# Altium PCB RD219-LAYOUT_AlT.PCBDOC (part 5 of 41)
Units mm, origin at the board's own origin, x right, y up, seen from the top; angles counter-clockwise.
Board outline 209.75 x 159.97 mm, 2 copper layers (TOP, BOTTOM), stack 0 mm thick; 398 components, 199 nets, 1469 pads, 0 vias.
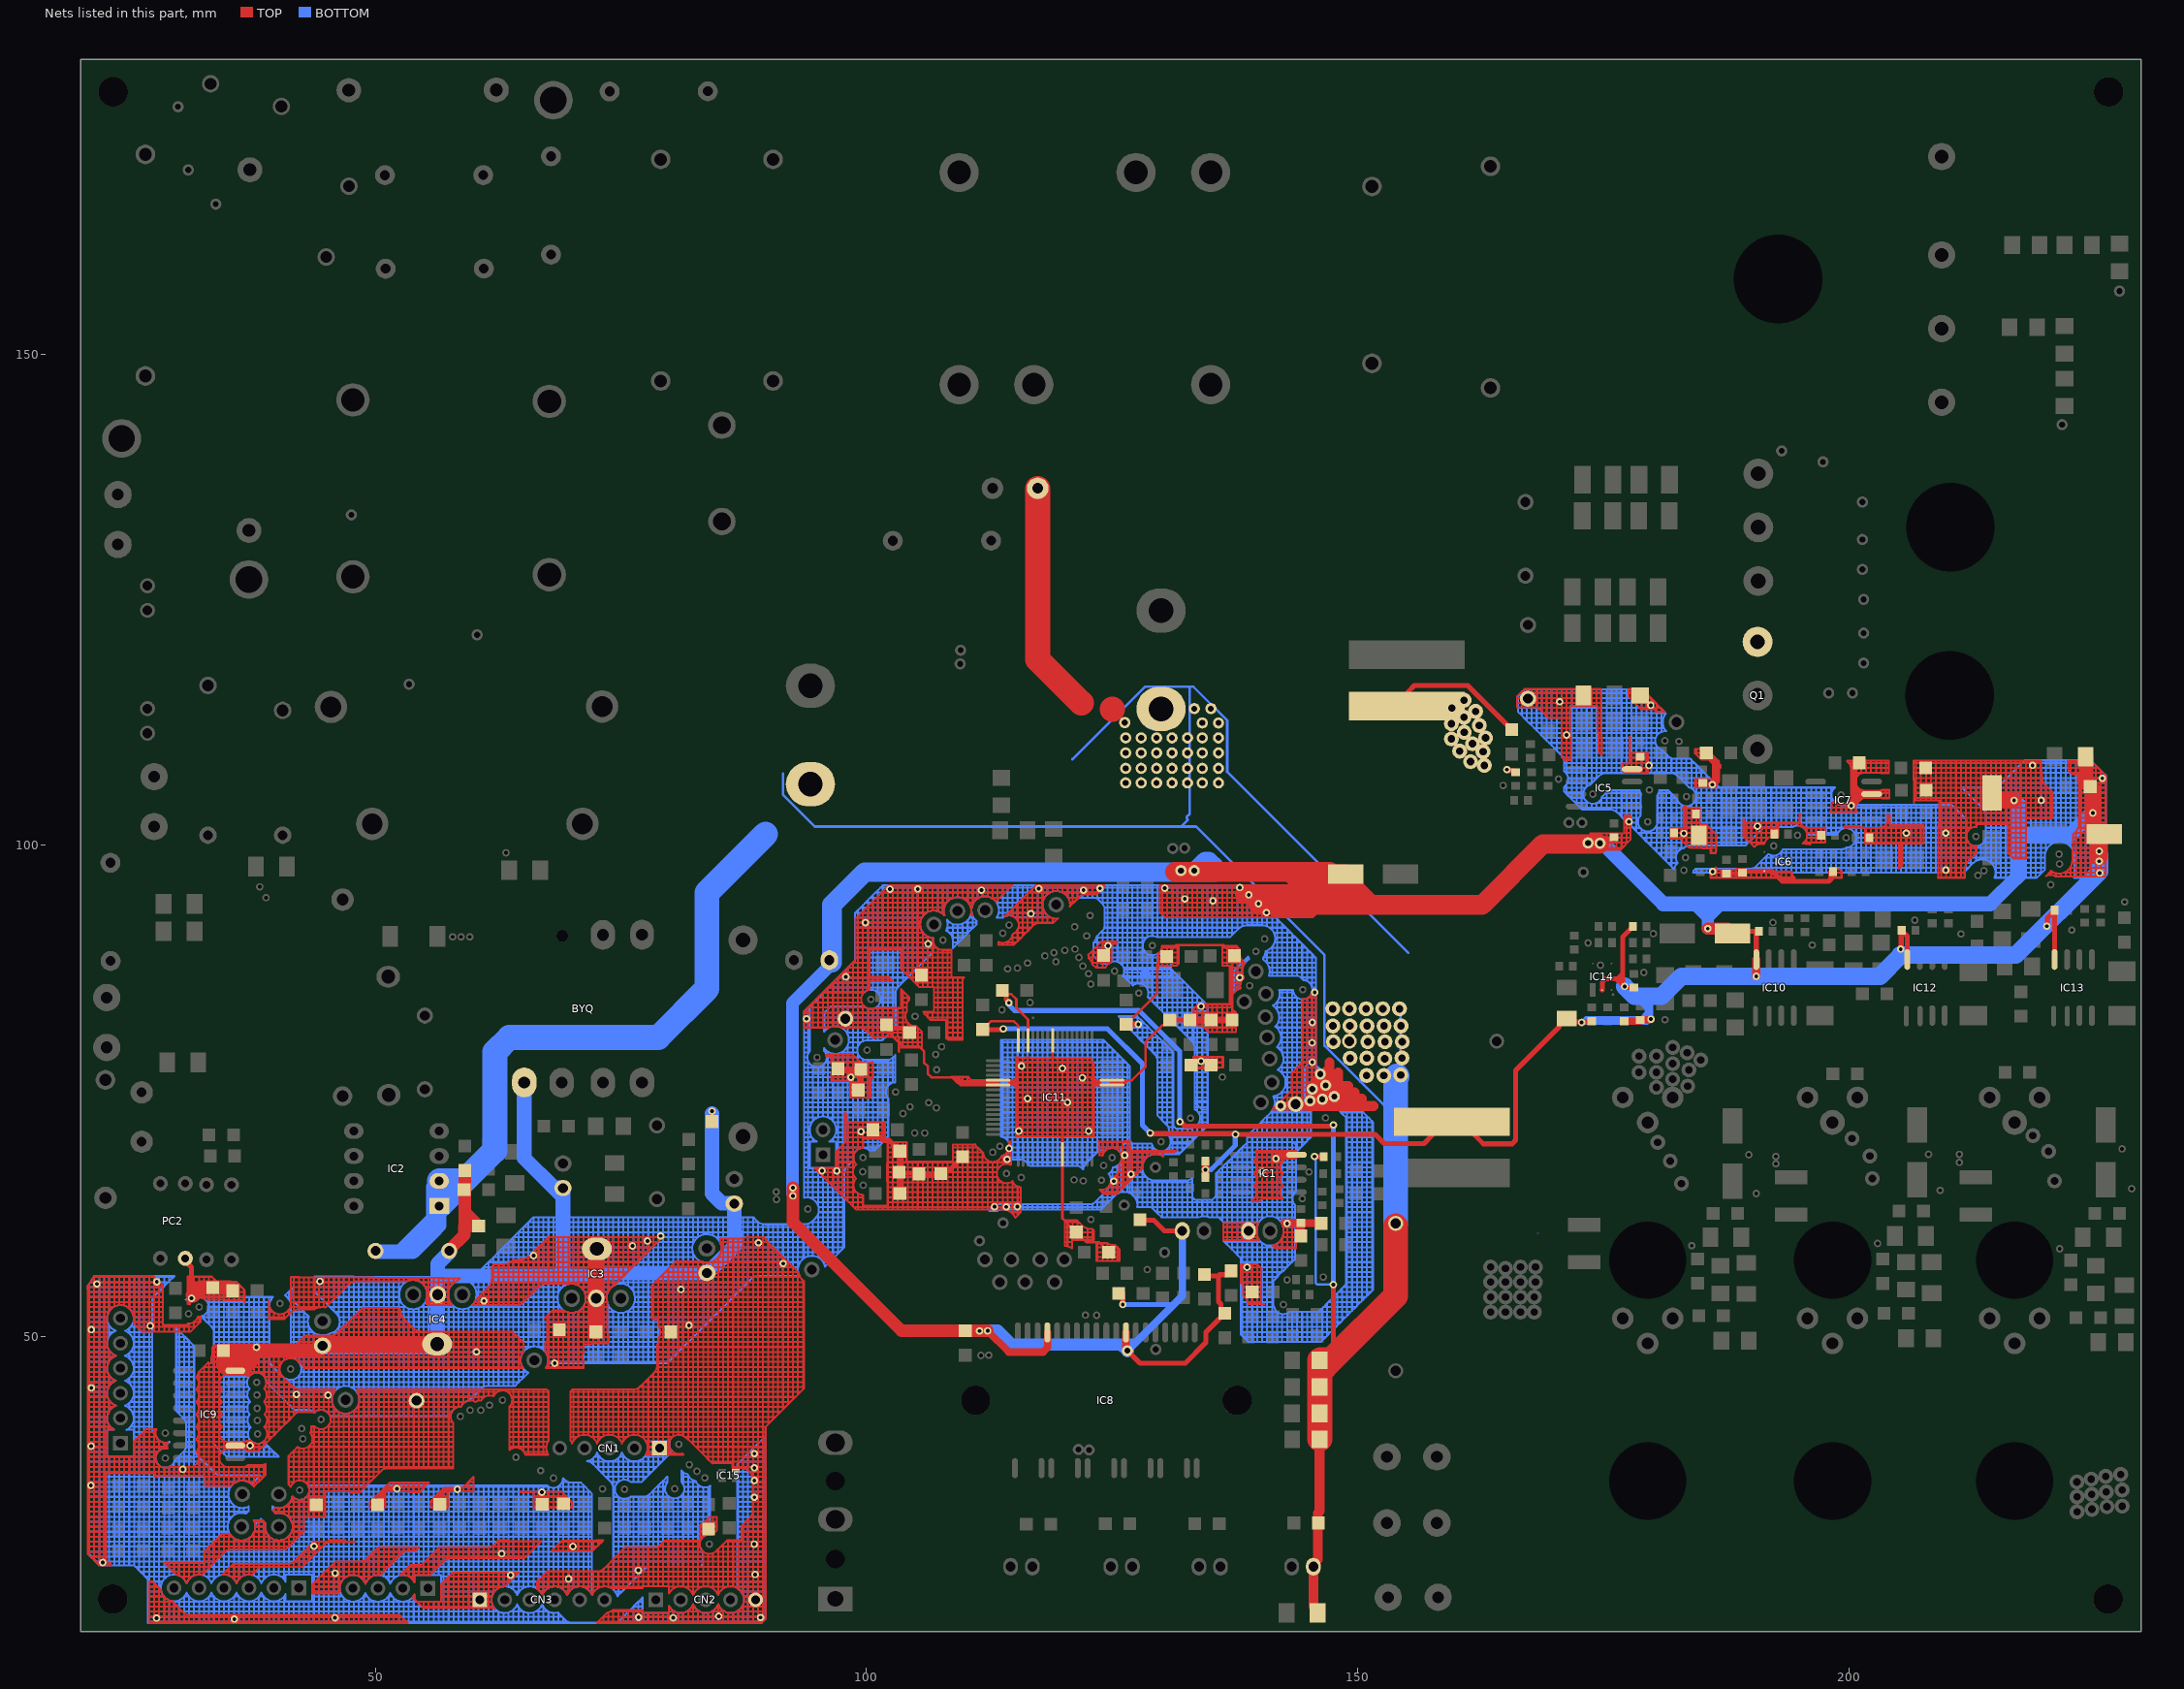
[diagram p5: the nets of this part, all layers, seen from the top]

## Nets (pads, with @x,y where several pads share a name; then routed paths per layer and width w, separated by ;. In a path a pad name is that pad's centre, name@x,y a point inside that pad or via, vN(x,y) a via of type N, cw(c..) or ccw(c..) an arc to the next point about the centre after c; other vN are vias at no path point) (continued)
GND: (continued)
  TOP w0.203: 32.573,41.336 33.081,41.336 ; 32.573,41.336 32.573,41.844 ; 32.573,41.844 32.573,42.352 ; 32.573,41.844 33.081,41.844 ; 32.573,42.352 32.573,42.86 ; 32.573,42.352 33.081,42.352 ; 32.573,42.86 32.573,43.368 ; 32.573,42.86 33.081,42.86 ; 32.573,43.368 33.081,43.368 ; 32.573,43.368 32.573,43.876 ; 32.573,43.876 33.081,43.876 ; 32.573,43.876 32.573,44.384 ; 32.573,44.384 32.573,44.892 ; 32.573,44.384 33.081,44.384 ; 32.573,44.892 32.573,45.4 ; 32.573,44.892 33.081,44.892 ; 32.573,45.4 32.573,45.908 ; 32.573,45.4 33.081,45.4 ; 32.573,45.908 32.573,46.416 ; 32.573,45.908 33.081,45.908 ; 32.573,46.416 32.573,46.924 ; 32.573,46.416 33.081,46.416 ; 32.573,46.924 33.081,46.924 ; 32.573,46.924 32.573,46.953 ; 32.573,46.953 32.943,47.323 ; 32.573,53.87 32.573,54.036 ; 32.573,54.036 32.573,54.544 ; 32.573,54.036 33.081,54.036 ; 32.573,54.544 32.573,55.001 32.573,55.052 ; 32.573,54.544 C30.2@33.081,54.544 ; 32.573,55.052 32.573,55.56 ; 32.573,55.052 C30.2@33.081,55.052 ; 32.573,55.56 32.573,56.068 ; 32.573,55.56 C30.2@33.081,55.56 ; 32.573,56.068 32.573,56.123 ; 32.573,56.068 33.081,56.068 ; 32.573,56.123 33.081,56.12 ; 32.631,27.112 32.631,27.62 ; 32.631,27.112 33.081,27.112 ; 32.631,27.62 32.631,28.128 ; 32.631,27.62 33.081,27.62 ; 32.631,28.128 33.081,28.128 ; 32.682,35.24 32.682,35.748 ; 32.682,35.24 33.081,35.24 ; 32.682,35.24 32.682,34.826 33.081,34.826 ; 32.682,35.748 33.081,35.748 ; 32.686,26.096 33.081,26.491 ; 32.712,28.253 cw(c32.197,28.768) 32.636,28.186 ccw(c32.197,28.768) 32.712,28.253 ; 32.712,28.253 33.095,28.636 ; 32.943,47.323 33.081,47.323 ; 33.081,20.889 33.081,21.016 ; 33.081,20.889 33.589,20.889 ; 33.081,21.016 33.081,21.524 ; 33.081,21.016 33.589,21.016 ; 33.081,21.524 33.081,21.692 ; 33.081,21.524 33.589,21.524 ; 33.081,21.692 33.589,21.692 ; 33.081,26.491 33.081,26.604 ; 33.081,26.491 33.194,26.604 ; 33.081,26.604 33.081,27.112 ; 33.081,26.604 33.194,26.604 ; 33.081,27.112 33.589,27.112 ; 33.081,27.112 33.081,27.62 ; 33.081,27.62 33.081,28.128 ; 33.081,27.62 33.589,27.62 ; 33.081,28.128 33.589,28.128 ; 33.081,34.826 33.589,34.826 ; 33.081,34.826 33.081,35.24 ; 33.081,35.24 33.081,35.748 ; 33.081,35.24 33.589,35.24 ; 33.081,35.748 33.081,36.256 ; 33.081,35.748 33.589,35.748 ; 33.081,36.256 33.081,36.764 ; 33.081,36.256 33.589,36.256 ; 33.081,36.764 33.081,37.272 ; 33.081,36.764 33.589,36.764 ; 33.081,37.272 33.081,37.78 ; 33.081,37.272 33.589,37.272 ; 33.081,37.78 33.081,38.288 ; 33.081,37.78 33.589,37.78 ; 33.081,38.288 33.081,38.796 ; 33.081,38.288 33.589,38.288 ; 33.081,38.796 33.081,39.304 ; 33.081,38.796 33.589,38.796 ; 33.081,39.304 33.081,39.812 ; 33.081,39.304 33.589,39.304 ; 33.081,39.812 33.081,40.32 ; 33.081,39.812 33.589,39.812 ; 33.081,40.32 33.081,40.828 ; 33.081,40.32 33.589,40.32 ; 33.081,40.828 33.589,40.828 ; 33.081,40.828 33.081,41.336 ; 33.081,41.336 33.589,41.336 ; 33.081,41.336 33.081,41.844 ; 33.081,41.844 33.081,42.352 ; 33.081,41.844 33.589,41.844 ; 33.081,42.352 33.081,42.86 ; 33.081,42.352 33.589,42.352 ; 33.081,42.86 33.081,43.368 ; 33.081,42.86 33.589,42.86 ; 33.081,43.368 33.589,43.368 ; 33.081,43.368 33.081,43.876 ; 33.081,43.876 33.589,43.876 ; 33.081,43.876 33.081,44.384 ; 33.081,44.384 33.081,44.892 ; 33.081,44.384 33.589,44.384 ; 33.081,44.892 33.081,45.4 ; 33.081,44.892 33.589,44.892 ; 33.081,45.4 33.081,45.908 ; 33.081,45.4 33.589,45.4 ; 33.081,45.908 33.081,46.416 ; 33.081,45.908 33.589,45.908 ; 33.081,46.416 33.081,46.924 ; 33.081,46.416 33.589,46.416 ; 33.081,46.924 33.589,46.924 ; 33.081,46.924 33.081,47.323 ; 33.081,47.323 33.317,47.323 33.317,47.432 ; 33.081,53.764 33.589,53.764 ; 33.081,53.764 33.081,54.036 ; 33.081,54.036 33.589,54.036 ; 33.081,54.036 C30.2@33.081,54.544 ; C30.2@33.081,54.544 33.081,55.001 C30.2@33.081,55.052 ; C30.2@33.081,54.544 C30.2@33.589,54.544 ; C30.2@33.081,55.052 C30.2@33.081,55.56 ; C30.2@33.081,55.052 C30.2@33.589,55.052 ; C30.2@33.081,55.56 33.081,56.068 ; C30.2@33.081,55.56 C30.2@33.589,55.56 ; 33.081,56.068 33.081,56.12 ; 33.081,56.068 33.395,56.068 ; 33.081,56.12 33.345,56.118 33.395,56.068 ; 33.095,28.636 33.589,29.13 ; 33.095,28.636 33.589,28.636 ; 33.194,26.604 33.589,26.999 ; 33.317,47.432 33.589,47.432 ; 33.351,47.94 cw(c32.065,48.356) 33.318,47.85 ccw(c32.065,48.356) 33.351,47.94 ; 33.351,47.94 ccw(c32.065,48.356) 33.417,48.356 ; 33.351,47.94 ccw(c32.065,48.356) 33.417,48.356 ; 33.351,47.94 33.589,47.94 ; 33.395,56.068 33.589,55.874 ; 33.417,48.356 33.417,48.448 ; 33.417,48.448 33.589,48.448 ; 33.417,48.448 33.417,48.914 33.458,48.956 ; 33.458,48.956 33.616,49.114 C48.2@34.097,49.114 ; 33.458,48.956 33.589,48.956 ; 33.589,20.889 33.589,21.016 ; 33.589,20.889 34.097,20.889 ; 33.589,21.016 33.589,21.524 ; 33.589,21.016 34.097,21.016 ; 33.589,21.524 33.589,21.692 ; 33.589,21.524 34.097,21.524 ; 33.589,21.692 34.097,21.692 ; 33.589,26.999 33.589,27.112 ; 33.589,26.999 33.702,27.112 ; 33.589,27.112 33.589,27.62 ; 33.589,27.112 33.702,27.112 ; 33.589,27.62 33.589,28.128 ; 33.589,27.62 34.097,27.62 ; 33.589,28.128 33.589,28.636 ; 33.589,28.128 34.097,28.128 ; 33.589,28.636 33.589,29.13 ; 33.589,28.636 34.097,28.636 ; 33.589,29.13 33.603,29.144 ; 33.589,34.826 34.097,34.826 ; 33.589,34.826 33.589,35.24 ; 33.589,35.24 33.589,35.748 ; 33.589,35.24 34.097,35.24 ; 33.589,35.748 33.589,36.256 ; 33.589,35.748 34.097,35.748 ; 33.589,36.256 33.589,36.764 ; 33.589,36.256 34.097,36.256 ; 33.589,36.764 33.589,37.272 ; 33.589,36.764 34.097,36.764 ; 33.589,37.272 33.589,37.78 ; 33.589,37.272 34.097,37.272 ; 33.589,37.78 33.589,38.288 ; 33.589,37.78 34.097,37.78 ; 33.589,38.288 33.589,38.796 ; 33.589,38.288 34.097,38.288 ; 33.589,38.796 33.589,39.304 ; 33.589,38.796 34.097,38.796 ; 33.589,39.304 33.589,39.812 ; 33.589,39.304 34.097,39.304 ; 33.589,39.812 33.589,40.32 ; 33.589,39.812 34.097,39.812 ; 33.589,40.32 33.589,40.828 ; 33.589,40.32 34.097,40.32 ; 33.589,40.828 34.097,40.828 ; 33.589,40.828 33.589,41.336 ; 33.589,41.336 34.097,41.336 ; 33.589,41.336 33.589,41.844 ; 33.589,41.844 33.589,42.352 ; 33.589,41.844 34.097,41.844 ; 33.589,42.352 33.589,42.86 ; 33.589,42.352 34.097,42.352 ; 33.589,42.86 33.589,43.368 ; 33.589,42.86 34.097,42.86 ; 33.589,43.368 34.097,43.368 ; 33.589,43.368 33.589,43.876 ; 33.589,43.876 34.097,43.876 ; 33.589,43.876 33.589,44.384 ; 33.589,44.384 33.589,44.892 ; 33.589,44.384 34.097,44.384 ; 33.589,44.892 33.589,45.4 ; 33.589,44.892 34.097,44.892 ; 33.589,45.4 33.589,45.908 ; 33.589,45.4 34.097,45.4 ; 33.589,45.908 33.589,46.416 ; 33.589,45.908 34.097,45.908 ; 33.589,46.416 33.589,46.924 ; 33.589,46.416 34.097,46.416 ; 33.589,46.924 33.589,47.432 ; 33.589,46.924 34.097,46.924 ; 33.589,47.432 33.589,47.94 ; 33.589,47.432 34.097,47.432 ; 33.589,47.94 33.589,48.448 ; 33.589,47.94 C48.2@34.097,47.94 ; 33.589,48.448 33.589,48.956 ; 33.589,48.448 C48.2@34.097,48.448 ; 33.589,48.956 C48.2@34.097,48.956 ; 33.589,53.764 33.589,54.036 ; 33.589,53.764 34.097,53.764 ; 33.589,54.036 C30.2@33.589,54.544 ; 33.589,54.036 34.097,54.036 ; C30.2@33.589,54.544 C30.2@34.097,54.544 ; C30.2@33.589,54.544 33.589,55.001 C30.2@33.589,55.052 ; C30.2@33.589,55.052 C30.2@33.589,55.56 ; C30.2@33.589,55.052 C30.2@34.097,55.052 ; C30.2@33.589,55.56 C30.2@34.097,55.56 ; C30.2@33.589,55.56 33.589,55.874 ; 33.589,55.874 33.632,55.831 ; 33.603,29.144 34.097,29.144 ; 33.603,29.144 34.097,29.638 ; 33.632,55.831 ccw(c34.237,56.436) C30.2@34.097,55.592 ; 33.632,55.831 ccw(c34.237,56.436) C30.2@34.097,55.592 ; 33.702,27.112 34.097,27.507 ; 34.097,20.889 34.097,21.016 ; 34.097,20.889 34.605,20.889 ; 34.097,21.016 34.097,21.524 ; 34.097,21.016 34.605,21.016 ; 34.097,21.524 34.097,21.692 ; 34.097,21.524 34.605,21.524 ; 34.097,21.692 34.605,21.692 ; 34.097,27.507 34.097,27.62 ; 34.097,27.507 34.21,27.62 ; 34.097,27.62 34.097,28.128 ; 34.097,27.62 34.21,27.62 ; 34.097,28.128 34.605,28.128 ; 34.097,28.128 34.097,28.636 ; 34.097,28.636 34.097,29.144 ; 34.097,28.636 34.605,28.636 ; 34.097,29.144 34.605,29.144 ; 34.097,29.144 34.097,29.638 ; 34.097,29.638 34.111,29.652 ; 34.097,34.826 34.605,34.826 ; 34.097,34.826 34.097,35.24 ; 34.097,35.24 34.097,35.748 ; 34.097,35.24 34.605,35.24 ; 34.097,35.748 34.097,36.256 ; 34.097,35.748 34.605,35.748 ; 34.097,36.256 34.097,36.764 ; 34.097,36.256 34.605,36.256 ; 34.097,36.764 34.097,37.272 ; 34.097,36.764 34.605,36.764 ; 34.097,37.272 34.097,37.78 ; 34.097,37.272 34.213,37.272 ; 34.097,37.78 34.097,38.288 ; 34.097,37.78 34.139,37.78 ; 34.097,38.288 34.097,38.796 ; 34.097,38.288 34.385,38.288 ; 34.097,38.796 34.097,39.304 ; 34.097,38.796 34.605,38.796 ; 34.097,39.304 34.097,39.812 ; 34.097,39.304 34.605,39.304 ; 34.097,39.812 34.097,40.32 ; 34.097,39.812 34.213,39.812 ; 34.097,40.32 34.097,40.828 ; 34.097,40.32 34.139,40.32 ; 34.097,40.828 34.097,41.336 ; 34.097,40.828 34.385,40.828 ; 34.097,41.336 34.097,41.844 ; 34.097,41.336 34.139,41.336 ; 34.097,41.844 34.097,42.352 ; 34.097,42.352 34.097,42.86 ; 34.097,42.352 34.213,42.352 ; 34.097,42.86 34.097,43.368 ; 34.097,42.86 34.139,42.86 ; 34.097,43.368 34.097,43.876 ; 34.097,43.368 34.385,43.368 ; 34.097,43.876 34.097,44.384 ; 34.097,43.876 34.139,43.876 ; 34.097,44.384 34.097,44.892 ; 34.097,44.892 34.097,45.4 ; 34.097,44.892 34.213,44.892 ; 34.097,45.4 34.097,45.908 ; 34.097,45.4 34.139,45.4 ; 34.097,45.908 34.097,46.416 ; 34.097,45.908 34.385,45.908 ; 34.097,46.416 34.097,46.924 ; 34.097,46.416 34.605,46.416 ; 34.097,46.924 34.097,47.432 ; 34.097,46.924 34.605,46.924 ; 34.097,47.432 C48.2@34.097,47.94 ; 34.097,47.432 34.554,47.432 34.605,47.432 ; C48.2@34.097,47.94 C48.2@34.097,48.448 ; C48.2@34.097,47.94 34.554,47.94 C48.2@34.605,47.94 ; C48.2@34.097,48.448 34.554,48.448 C48.2@34.605,48.448 ; C48.2@34.097,48.448 C48.2@34.097,48.956 ; C48.2@34.097,48.956 C48.2@34.097,49.114 ; C48.2@34.097,48.956 C48.2@34.605,48.956 ; C48.2@34.097,49.114 C48.2@34.605,49.114 ; 34.097,53.764 34.097,54.036 ; 34.097,53.764 34.605,53.764 ; 34.097,54.036 C30.2@34.097,54.544 ; 34.097,54.036 34.605,54.036 ; C30.2@34.097,54.544 34.605,54.544 ; C30.2@34.097,54.544 34.097,55.001 C30.2@34.097,55.052 ; C30.2@34.097,55.052 C30.2@34.097,55.56 ; C30.2@34.097,55.052 34.605,55.052 ; C30.2@34.097,55.56 34.605,55.56 ; C30.2@34.097,55.56 C30.2@34.097,55.592 ; C30.2@34.097,55.592 ccw(c34.237,56.436) 34.237,55.581 ; C30.2@34.097,55.592 ccw(c34.237,56.436) 34.237,55.581 ; 34.111,29.652 34.399,29.939 34.605,29.939 ; 34.111,29.652 34.605,29.652 ; 34.139,37.78 ccw(c35.05,37.653) 34.213,37.272 ; 34.139,37.78 cw(c35.05,37.653) 34.385,38.288 ; 34.139,40.32 ccw(c35.05,40.193) 34.21,39.819 ccw(c35.05,40.193) 34.213,39.812 ; 34.139,40.32 cw(c35.05,40.193) 34.385,40.828 ; 34.139,41.336 ccw(c35.05,41.463) 34.385,40.828 ; 34.139,42.86 ccw(c35.05,42.733) 34.21,42.359 ccw(c35.05,42.733) 34.213,42.352 ; 34.139,42.86 cw(c35.05,42.733) 34.385,43.368 ; 34.139,43.876 ccw(c35.05,44.003) 34.385,43.368 ; 34.139,45.4 ccw(c35.05,45.273) 34.21,44.899 ccw(c35.05,45.273) 34.213,44.892 ; 34.139,45.4 cw(c35.05,45.273) 34.385,45.908 ; 34.21,27.62 34.605,28.015 ; 34.237,55.581 34.605,55.581 ; 34.385,45.908 cw(c35.05,45.273) 34.605,46.077 ; 34.605,20.889 35.113,20.889 ; 34.605,20.889 34.605,21.016 ; 34.605,21.016 35.113,21.016 ; 34.605,21.016 34.605,21.524 ; 34.605,21.524 35.113,21.524 ; 34.605,21.524 34.605,21.692 ; 34.605,21.692 35.113,21.692 ; 34.605,25.797 cw(c34.605,24.445) 35.113,25.698 ; 34.605,25.797 34.605,25.955 ; 34.605,25.955 34.746,26.096 ; 34.605,28.015 34.605,28.128 ; 34.605,28.015 34.725,28.135 ; 34.605,28.128 34.605,28.636 ; 34.605,28.636 34.605,29.144 ; 34.605,28.636 35.113,28.636 ; 34.605,29.144 34.605,29.652 ; 34.605,29.144 35.113,29.144 ; 34.605,29.652 34.605,29.939 ; 34.605,29.652 35.113,29.652 ; 34.605,29.939 35.113,29.939 ; 34.605,34.826 35.113,34.826 ; 34.605,34.826 34.605,35.24 ; 34.605,35.24 34.605,35.748 ; 34.605,35.24 35.113,35.24 ; 34.605,35.748 35.113,35.748 ; 34.605,35.748 34.605,36.256 ; 34.605,36.256 34.605,36.764 ; 34.605,36.256 35.113,36.256 ; 34.605,36.764 34.816,36.764 ; 34.605,36.764 34.605,36.849 ccw(c35.05,37.653) 34.812,36.765 ccw(c35.05,37.653) 34.816,36.764 ; 34.605,38.796 IC9.2@35.113,38.796 ; 34.605,38.796 34.605,39.304 ; 34.605,38.796 34.605,38.457 cw(c35.05,37.653) 35.05,38.572 35.113,38.572 ; 34.605,39.304 34.816,39.304 ; 34.605,39.304 34.605,39.389 ccw(c35.05,40.193) 34.812,39.305 ccw(c35.05,40.193) 34.816,39.304 ; 34.605,46.077 cw(c35.05,45.273) 35.05,46.192 35.113,46.192 ; 34.605,46.077 34.605,46.416 ; 34.605,46.416 34.605,46.924 ; 34.605,46.416 IC9.8@35.113,46.416 ; 34.605,46.924 34.605,47.065 34.605,47.432 ; 34.605,46.924 34.746,46.924 35.113,46.924 ; 34.605,47.432 34.605,47.686 C48.2@34.605,47.94 ; 34.605,47.432 35.113,47.432 ; C48.2@34.605,47.94 C48.2@34.605,48.448 ; C48.2@34.605,47.94 C48.2@35.113,47.94 ; C48.2@34.605,48.448 C48.2@35.113,48.448 ; C48.2@34.605,48.448 34.605,48.575 C48.2@34.605,48.956 ; C48.2@34.605,48.956 C48.2@34.605,49.114 ; C48.2@34.605,48.956 C48.2@35.113,48.956 ; C48.2@34.605,49.114 C48.2@35.113,49.114 ; 34.605,53.764 34.605,54.036 ; 34.605,54.036 34.605,54.544 ; 34.605,54.036 R49.1@35.113,54.036 ; 34.605,54.544 R49.1@35.113,54.544 ; 34.605,54.544 34.605,55.001 34.605,55.052 ; 34.605,55.052 34.605,55.56 ; 34.605,55.052 R49.1@35.113,55.052 ; 34.605,55.56 35.113,55.56 ; 34.605,55.56 34.605,55.581 ; 34.605,55.581 35.113,55.581 ; 34.725,28.135 cw(c35.24,27.62) 35.113,28.337 ; 34.725,28.135 cw(c35.24,27.62) 35.113,28.337 ; 34.746,26.096 35.113,26.096 ; 34.746,26.096 35.113,26.463 ; 34.816,36.764 ccw(c35.05,37.653) 35.05,36.734 35.113,36.734 ; 34.816,39.304 ccw(c35.05,40.193) 35.05,39.274 35.113,39.274 ; 35.113,20.889 35.113,21.016 ; 35.113,20.889 35.621,20.889 ; 35.113,21.016 pad.@35.621,21.016 ; 35.113,21.016 35.113,21.524 ; 35.113,21.524 35.113,21.692 ; 35.113,21.524 pad.@35.621,21.524 ; 35.113,21.692 35.621,21.692 ; 35.113,25.698 cw(c34.605,24.445) 35.321,25.591 cw(c34.605,24.445) 35.326,25.588 ; 35.113,25.698 35.113,26.096 ; 35.113,26.096 35.621,26.096 ; 35.113,26.096 35.113,26.463 ; 35.113,26.463 35.254,26.604 ; 35.113,28.337 cw(c35.24,27.62) 35.24,28.349 ; 35.113,28.337 cw(c35.24,27.62) 35.24,28.349 ; 35.113,28.337 35.113,28.636 ; 35.113,28.636 35.113,29.144 ; 35.113,28.636 35.621,28.636 ; 35.113,29.144 35.113,29.652 ; 35.113,29.144 35.621,29.144 ; 35.113,29.652 35.113,29.939 ; 35.113,29.652 35.417,29.652 ; 35.113,29.939 35.186,29.939 ; 35.113,34.826 35.113,35.24 ; 35.113,35.24 35.113,35.748 ; 35.113,35.24 35.621,35.24 ; 35.113,35.748 35.621,35.748 ; 35.113,35.748 35.113,36.256 ; 35.113,36.256 35.113,36.734 ; 35.113,36.256 35.621,36.256 ; 35.113,36.734 35.621,36.734 ; 35.113,38.572 IC9.2@35.113,38.796 ; 35.113,38.572 35.621,38.572 ; IC9.2@35.113,38.796 IC9.2@35.621,38.796 ; IC9.2@35.113,38.796 35.113,39.274 ; 35.113,39.274 35.621,39.274 ; 35.113,46.192 IC9.8@35.113,46.416 ; 35.113,46.192 35.621,46.192 ; IC9.8@35.113,46.416 IC9.8@35.621,46.416 ; IC9.8@35.113,46.416 35.113,46.762 35.113,46.924 ; 35.113,46.924 35.113,47.432 ; 35.113,46.924 35.621,46.924 ; 35.113,47.432 35.113,47.686 C48.2@35.113,47.94 ; 35.113,47.432 35.621,47.432 ; C48.2@35.113,47.94 C48.2@35.113,48.448 ; C48.2@35.113,47.94 35.621,47.94 ; C48.2@35.113,48.448 35.621,48.448 ; C48.2@35.113,48.448 35.113,48.575 C48.2@35.113,48.956 ; C48.2@35.113,48.956 C48.2@35.113,49.114 ; C48.2@35.113,48.956 35.621,48.956 ; C48.2@35.113,49.114 35.621,49.114 ; 35.113,53.727 R49.1@35.113,54.036 ; 35.113,53.727 35.621,53.727 ; R49.1@35.113,54.036 R49.1@35.113,54.544 ; R49.1@35.113,54.036 R49.1@35.621,54.036 ; R49.1@35.113,54.544 R49.1@35.621,54.544 ; R49.1@35.113,54.544 35.113,55.001 R49.1@35.113,55.052 ; R49.1@35.113,55.052 35.113,55.56 ; R49.1@35.113,55.052 R49.1@35.621,55.052 ; 35.113,55.56 35.621,55.56 ; 35.113,55.56 35.113,55.581 ; 35.113,55.581 35.621,55.581 ; 35.186,29.939 ccw(c36.383,30.668) 35.409,29.66 ccw(c36.383,30.668) 35.417,29.652 ; 35.24,28.349 35.621,28.349 ; 35.254,26.604 35.621,26.604 ; 35.254,26.604 35.542,26.891 35.621,26.891 ; 35.326,25.588 cw(c34.605,24.445) 35.621,25.336 ; 35.326,25.588 35.621,25.588 ; 35.417,29.652 ccw(c36.383,30.668) 35.62,29.493 ccw(c36.383,30.668) 35.621,29.492 ; 35.621,20.889 pad.@35.621,21.016 ; 35.621,20.889 36.129,20.889 ; pad.@35.621,21.016 36.129,21.016 ; pad.@35.621,21.016 pad.@35.621,21.524 ; pad.@35.621,21.524 35.621,21.692 ; pad.@35.621,21.524 36.129,21.524 ; 35.621,21.692 36.129,21.692 ; 35.621,25.336 cw(c34.605,24.445) 35.798,25.08 ; 35.621,25.336 35.621,25.588 ; 35.621,25.588 35.621,26.096 ; 35.621,25.588 36.129,25.588 ; 35.621,26.096 36.129,26.096 ; 35.621,26.096 35.621,26.604 ; 35.621,26.604 36.129,26.604 ; 35.621,26.604 35.621,26.891 ; 35.621,26.891 36.129,26.891 ; 35.621,28.349 35.621,28.636 ; 35.621,28.349 36.129,28.349 ; 35.621,28.636 35.621,29.144 ; 35.621,28.636 36.129,28.636 ; 35.621,29.144 36.129,29.144 ; 35.621,29.144 35.621,29.492 ; 35.621,35.09 cw(c36.463,33.97) 35.87,35.24 35.621,35.24 ; 35.621,35.09 35.621,35.24 ; 35.621,35.24 35.621,35.748 ; 35.621,35.748 35.621,36.256 ; 35.621,35.748 36.129,35.748 ; 35.621,36.256 35.621,36.734 ; 35.621,36.256 36.129,36.256 ; 35.621,36.734 36.129,36.734 ; 35.621,38.572 IC9.2@35.621,38.796 ; 35.621,38.572 36.129,38.572 ; IC9.2@35.621,38.796 IC9.2@36.129,38.796 ; IC9.2@35.621,38.796 35.621,39.274 ; 35.621,39.274 36.129,39.274 ; 35.621,46.192 IC9.8@35.621,46.416 ; 35.621,46.192 36.129,46.192 ; IC9.8@35.621,46.416 35.621,46.762 35.621,46.924 ; IC9.8@35.621,46.416 IC9.8@36.129,46.416 ; 35.621,46.924 35.621,47.432 ; 35.621,46.924 36.129,46.924 ; 35.621,47.432 35.621,47.686 35.621,47.94 ; 35.621,47.432 36.129,47.432 ; 35.621,47.94 35.621,48.448 ; 35.621,47.94 36.129,47.94 ; 35.621,48.448 35.621,48.575 35.621,48.956 ; 35.621,48.448 36.129,48.448 ; 35.621,48.956 35.621,49.114 ; 35.621,48.956 36.129,48.956 ; 35.621,49.114 36.129,49.114 ; 35.621,53.727 R49.1@35.621,54.036 ; 35.621,53.727 36.129,53.727 ; R49.1@35.621,54.036 R49.1@35.621,54.544 ; R49.1@35.621,54.036 R49.1@36.129,54.036 ; R49.1@35.621,54.544 R49.1@36.129,54.544 ; R49.1@35.621,54.544 R49.1@35.621,55.052 ; R49.1@35.621,55.052 35.621,55.56 ; R49.1@35.621,55.052 R49.1@36.129,55.052 ; 35.621,55.56 35.884,55.56 ; 35.621,55.56 35.621,55.581 ; 35.621,55.581 35.864,55.581 35.884,55.56 ; 35.798,25.08 cw(c34.605,24.445) 35.875,24.908 cw(c37.145,24.445) 35.952,25.08 ; 35.798,25.08 35.952,25.08 ; 35.884,55.56 R49.1@36.129,55.315 ; 36.129,20.889 36.129,21.016 ; 36.129,20.889 36.637,20.889 ; 36.129,21.016 36.637,21.016 ; 36.129,21.016 36.129,21.524 ; 36.129,21.524 36.129,21.692 ; 36.129,21.524 36.637,21.524 ; 36.129,21.692 36.637,21.692 ; 36.129,25.588 36.129,26.096 ; 36.129,25.588 36.424,25.588 ; 36.129,26.096 36.129,26.604 ; 36.129,26.096 36.637,26.096 ; 36.129,26.604 36.129,26.891 ; 36.129,26.604 36.637,26.604 ; 36.129,26.891 36.637,26.891 ; 36.129,28.349 36.129,28.636 ; 36.129,28.349 36.637,28.349 ; 36.129,28.636 36.129,29.144 ; 36.129,28.636 36.637,28.636 ; 36.129,29.144 36.637,29.144 ; 36.129,35.331 cw(c36.463,33.97) 36.637,35.361 ; 36.129,35.331 36.129,35.748 ; 36.129,35.748 36.637,35.748 ; 36.129,35.748 36.129,36.256 ; 36.129,36.256 36.129,36.734 ; 36.129,36.256 36.637,36.256 ; 36.129,36.734 36.447,36.734 ccw(c36.447,37.653) 36.637,36.754 ; 36.129,38.572 IC9.2@36.129,38.796 ; 36.129,38.572 36.447,38.572 cw(c36.447,37.653) 36.637,38.552 ; IC9.2@36.129,38.796 IC9.2@36.637,38.796 ; IC9.2@36.129,38.796 36.129,38.923 36.129,39.274 ; 36.129,39.274 36.447,39.274 ccw(c36.447,40.193) 36.637,39.294 ; 36.129,46.192 IC9.8@36.129,46.416 ; 36.129,46.192 36.447,46.192 cw(c36.447,45.273) 36.637,46.172 ; IC9.8@36.129,46.416 IC9.8@36.637,46.416 ; IC9.8@36.129,46.416 36.129,46.762 36.129,46.924 ; 36.129,46.924 36.129,47.432 ; 36.129,46.924 36.637,46.924 ; 36.129,47.432 36.129,47.686 36.129,47.94 ; 36.129,47.432 36.637,47.432 ; 36.129,47.94 36.129,48.448 ; 36.129,47.94 36.637,47.94 ; 36.129,48.448 36.129,48.575 36.129,48.956 ; 36.129,48.448 36.637,48.448 ; 36.129,48.956 36.129,49.114 ; 36.129,48.956 36.637,48.956 ; 36.129,49.114 36.637,49.114 ; 36.129,53.727 R49.1@36.129,54.036 ; 36.129,53.727 36.637,53.727 ; R49.1@36.129,54.036 R49.1@36.129,54.544 ; R49.1@36.129,54.036 36.637,54.036 ; R49.1@36.129,54.544 36.637,54.544 ; R49.1@36.129,54.544 R49.1@36.129,55.052 ; R49.1@36.129,55.052 R49.1@36.129,55.315 ; R49.1@36.129,55.052 36.392,55.052 ; R49.1@36.129,55.315 36.392,55.052 ; 36.392,55.052 36.637,54.807 ; 36.424,25.588 cw(c37.145,24.445) 36.429,25.591 cw(c37.145,24.445) 36.637,25.697 ; 36.637,20.889 36.637,21.016 ; 36.637,20.889 37.145,20.889 ; 36.637,21.016 36.637,21.524 ; 36.637,21.016 37.145,21.016 ; 36.637,21.524 36.637,21.692 ; 36.637,21.524 37.145,21.524 ; 36.637,21.692 37.145,21.692 ; 36.637,25.697 cw(c37.145,24.445) 36.639,25.698 cw(c37.145,24.445) 37.145,25.797 ; 36.637,25.698 36.637,26.096 ; 36.637,26.096 36.637,26.604 ; 36.637,26.096 37.145,26.096 ; 36.637,26.604 36.637,26.891 ; 36.637,26.604 37.145,26.604 ; 36.637,26.891 37.145,26.891 ; 36.637,28.349 36.637,28.636 ; 36.637,28.349 37.145,28.349 ; 36.637,28.636 36.637,29.144 ; 36.637,28.636 37.145,28.636 ; 36.637,29.144 37.145,29.144 ; 36.637,29.144 36.637,29.29 ; 36.637,35.361 cw(c36.463,33.97) 37.056,35.24 ; 36.637,35.361 36.637,35.748 ; 36.637,35.748 37.145,35.748 ; 36.637,35.748 36.637,36.256 ; 36.637,36.256 37.145,36.256 ; 36.637,36.256 36.637,36.754 ; 36.637,36.754 ccw(c36.447,37.653) 36.68,36.764 ; 36.637,38.552 cw(c36.447,37.653) 37.007,38.382 ; 36.637,38.552 IC9.2@36.637,38.796 ; IC9.2@36.637,38.796 pad.@37.145,38.796 ; IC9.2@36.637,38.796 36.637,38.923 36.637,39.294 ; 36.637,39.294 ccw(c36.447,40.193) 36.68,39.304 ; 36.637,46.172 cw(c36.447,45.273) 36.946,46.045 ; 36.637,46.172 IC9.8@36.637,46.416 ; IC9.8@36.637,46.416 37.145,46.416 ; IC9.8@36.637,46.416 36.637,46.836 36.637,46.924 ; 36.637,46.924 36.637,47.432 ; 36.637,46.924 36.725,46.924 37.145,46.924 ; 36.637,47.432 36.637,47.686 36.637,47.94 ; 36.637,47.432 37.145,47.432 ; 36.637,47.94 36.637,48.448 ; 36.637,47.94 37.018,47.94 37.145,47.94 ; 36.637,48.448 36.637,48.575 36.637,48.956 ; 36.637,48.448 37.145,48.448 ; 36.637,48.956 36.637,49.114 ; 36.637,48.956 37.145,48.956 ; 36.637,49.114 37.145,49.114 ; 36.637,53.727 36.637,54.036 ; 36.637,54.036 36.637,54.544 ; 36.637,54.036 36.732,54.036 ; 36.637,54.544 36.732,54.544 ; 36.637,54.544 36.637,54.807 ; 36.637,54.807 36.732,54.713 36.732,54.544 ; 36.68,36.764 ccw(c36.447,37.653) 37.007,36.924 ; 36.68,36.764 37.145,36.764 ; 36.68,39.304 37.145,39.304 ; 36.732,54.036 36.732,54.544 ; 36.946,46.045 37.145,46.045 ; 37.007,36.924 37.145,36.924 ; 37.007,38.382 37.145,38.382 ; 37.056,35.24 cw(c36.463,33.97) 37.145,35.194 ; 37.056,35.24 37.145,35.24 ; 37.145,20.889 37.145,21.016 ; 37.145,20.889 37.653,20.889 ; 37.145,21.016 37.145,21.524 ; 37.145,21.016 37.653,21.016 ; 37.145,21.524 37.145,21.692 ; 37.145,21.524 37.653,21.524 ; 37.145,21.692 37.653,21.692 ; 37.145,25.797 37.145,26.096 ; 37.145,26.096 37.653,26.096 ; 37.145,26.096 37.145,26.604 ; 37.145,26.604 37.653,26.604 ; 37.145,26.604 37.145,26.891 ; 37.145,26.891 37.653,26.891 ; 37.145,28.349 37.145,28.636 ; 37.145,28.349 37.653,28.349 ; 37.145,28.636 37.145,29.144 ; 37.145,28.636 37.653,28.636 ; 37.145,29.144 37.653,29.144 ; 37.145,35.194 37.145,35.24 ; 37.145,35.24 37.145,35.748 ; 37.145,35.24 37.653,35.24 ; 37.145,35.748 37.145,36.256 ; 37.145,35.748 37.653,35.748 ; 37.145,36.256 37.145,36.764 ; 37.145,36.256 37.653,36.256 ; 37.145,36.764 37.653,36.764 ; 37.145,36.764 37.145,36.924 ; 37.145,36.924 37.653,36.924 ; 37.145,38.382 pad.@37.145,38.796 ; 37.145,38.382 37.653,38.382 ; pad.@37.145,38.796 37.653,38.796 ; pad.@37.145,38.796 37.145,38.923 37.145,39.304 ; 37.145,39.304 37.145,39.423 ; 37.145,39.304 37.461,39.304 ; 37.145,39.423 37.321,39.423 ; 37.145,46.045 37.145,46.416 ; 37.145,46.045 37.226,46.045 ; 37.145,46.416 37.145,46.924 ; 37.145,46.416 37.653,46.416 ; 37.145,46.924 37.145,47.344 37.145,47.432 ; 37.145,46.924 37.653,46.924 ; 37.145,47.432 37.145,47.94 ; 37.145,47.432 37.233,47.432 37.653,47.432 ; 37.145,47.94 37.145,48.067 37.145,48.448 ; 37.145,47.94 37.442,47.94 37.653,47.94 ; 37.145,48.448 37.145,48.575 37.145,48.956 ; 37.145,48.448 37.526,48.448 37.653,48.448 ; 37.145,48.956 37.145,49.114 ; 37.145,48.956 pad.@37.653,48.956 ; 37.145,49.114 pad.@37.653,49.114 ; 37.226,46.045 cw(c37.93,45.359) 37.653,46.302 ; 37.321,39.423 ccw(c38.024,40.11) 37.461,39.304 ; 37.349,29.652 ccw(c36.383,30.668) 37.357,29.66 ccw(c36.383,30.668) 37.653,30.075 37.653,29.652 ; 37.349,29.652 37.653,29.652 ; 37.461,39.304 ccw(c38.024,40.11) 37.653,39.2 ; 37.653,20.889 37.653,21.016 ; 37.653,20.889 38.161,20.889 ; 37.653,21.016 37.653,21.524 ; 37.653,21.016 38.161,21.016 ; 37.653,21.524 37.653,21.692 ; 37.653,21.524 38.161,21.524 ; 37.653,21.692 38.161,21.692 ; 37.653,25.983 37.653,26.096 ; 37.653,25.983 37.766,26.096 ; 37.653,26.096 37.653,26.604 ; 37.653,26.096 37.766,26.096 ; 37.653,26.604 38.161,26.604 ; 37.653,26.604 37.653,26.891 ; 37.653,26.891 38.161,26.891 ; 37.653,28.349 37.653,28.636 ; 37.653,28.349 38.161,28.349 ; 37.653,28.636 37.653,29.144 ; 37.653,28.636 38.161,28.636 ; 37.653,29.144 37.653,29.652 ; 37.653,29.144 38.161,29.144 ; 37.653,29.652 38.161,29.652 ; 37.653,35.24 37.653,35.748 ; 37.653,35.748 38.161,35.748 ; 37.653,35.748 37.653,36.256 ; 37.653,36.256 37.653,36.764 ; 37.653,36.256 38.161,36.256 ; 37.653,36.764 38.161,36.764 ; 37.653,36.764 37.653,36.924 ; 37.653,36.924 38.161,36.924 ; 37.653,38.382 37.653,38.796 ; 37.653,38.382 38.108,38.382 38.161,38.435 ; 37.653,38.796 38.161,38.796 ; 37.653,38.796 37.653,39.2 ; 37.653,39.2 ccw(c38.024,40.11) 38.161,39.137 ; 37.653,46.302 cw(c37.93,45.359) 38.161,46.314 ; 37.653,46.302 37.653,46.416 ; 37.653,46.416 37.653,46.924 ; 37.653,46.416 38.161,46.416 ; 37.653,46.924 37.653,47.432 ; 37.653,46.924 38.161,46.924 ; 37.653,47.432 37.653,47.94 ; 37.653,47.432 38.161,47.432 ; 37.653,47.94 37.653,48.448 ; 37.653,47.94 38.161,47.94 ; 37.653,48.448 37.653,48.575 pad.@37.653,48.956 ; 37.653,48.448 38.161,48.448 ; pad.@37.653,48.956 pad.@37.653,49.114 ; pad.@37.653,48.956 pad.@38.161,48.956 ; pad.@37.653,49.114 pad.@38.161,49.114 ; 37.689,30.16 ccw(c36.383,30.668) 37.785,30.668 ; 37.689,30.16 38.161,30.16 ; 37.689,31.176 cw(c36.383,30.668) 37.785,30.668 ; 37.689,31.176 38.161,31.176 ; 37.766,26.096 38.04,26.37 ; 37.785,30.668 38.161,30.668 ; 38.04,26.37 cw(c38.555,25.855) 38.161,26.468 ; 38.04,26.37 cw(c38.555,25.855) 38.161,26.468 ; 38.161,20.889 38.161,21.016 ; 38.161,20.889 38.669,20.889 ; 38.161,21.016 38.161,21.524 ; 38.161,21.016 38.669,21.016 ; 38.161,21.524 38.161,21.692 ; 38.161,21.524 38.669,21.524 ; 38.161,21.692 38.669,21.692 ; 38.161,26.468 cw(c38.555,25.855) 38.555,26.584 ; 38.161,26.468 cw(c38.555,25.855) 38.555,26.584 ; 38.161,26.468 38.161,26.604 ; 38.161,26.604 38.669,26.604 ; 38.161,26.604 38.161,26.891 ; 38.161,26.891 38.669,26.891 ; 38.161,28.349 38.669,28.349 ; 38.161,28.349 38.161,28.636 ; 38.161,28.636 38.161,29.144 ; 38.161,28.636 38.669,28.636 ; 38.161,29.144 38.669,29.144 ; 38.161,29.144 38.161,29.652 ; 38.161,29.652 38.161,30.16 ; 38.161,29.652 38.669,29.652 ; 38.161,30.16 38.161,30.668 ; 38.161,30.16 38.669,30.16 ; 38.161,30.668 38.669,30.668 ; 38.161,30.668 38.161,31.176 ; 38.161,31.176 38.161,31.336 ; 38.161,31.176 38.655,31.176 ; 38.161,31.336 38.494,31.336 38.655,31.176 ; 38.161,35.748 38.161,36.256 ; 38.161,36.256 38.161,36.764 ; 38.161,36.256 38.669,36.256 ; 38.161,36.764 38.161,36.924 ; 38.161,36.764 38.669,36.764 ; 38.161,36.924 38.41,36.924 ; 38.161,38.435 38.161,38.796 ; 38.161,38.435 38.522,38.796 ; 38.161,38.796 38.522,38.796 ; 38.161,38.796 38.161,39.137 ; 38.161,39.137 ccw(c38.024,40.11) 38.586,39.304 ; 38.161,46.314 cw(c37.93,45.359) 38.669,46.007 ; 38.161,46.314 38.161,46.416 ; 38.161,46.416 38.161,46.924 ; 38.161,46.416 38.669,46.416 ; 38.161,46.924 38.161,47.432 ; 38.161,46.924 38.669,46.924 ; 38.161,47.432 38.161,47.94 ; 38.161,47.432 38.669,47.432 ; 38.161,47.94 38.161,48.448 ; 38.161,47.94 38.669,47.94 ; 38.161,48.448 38.161,48.575 pad.@38.161,48.956 ; 38.161,48.448 38.669,48.448 ; pad.@38.161,48.956 pad.@38.161,49.114 ; pad.@38.161,48.956 38.669,48.956 ; pad.@38.161,49.114 38.669,49.114 ; 38.41,36.924 ccw(c38.41,37.653) 38.669,36.972 ; 38.41,36.924 ccw(c38.41,37.653) 38.669,36.972 ; 38.522,38.796 38.669,38.943 ; 38.555,26.584 38.669,26.584 ; 38.586,39.304 38.669,39.304 ; 38.655,31.176 38.669,31.162 ; 38.669,20.889 39.177,20.889 ; 38.669,20.889 38.669,21.016 ; 38.669,21.016 39.177,21.016 ; 38.669,21.016 38.669,21.524 ; 38.669,21.524 38.669,21.692 ; 38.669,21.524 39.177,21.524 ; 38.669,21.692 39.177,21.692 ; 38.669,26.584 39.177,26.584 ; 38.669,26.584 38.669,26.604 ; 38.669,26.604 39.177,26.604 ; 38.669,26.604 38.669,26.891 ; 38.669,26.891 39.177,26.891 ; 38.669,28.349 39.177,28.349 ; 38.669,28.349 38.669,28.636 ; 38.669,28.636 38.669,29.144 ; 38.669,28.636 39.177,28.636 ; 38.669,29.144 39.177,29.144 ; 38.669,29.144 38.669,29.652 ; 38.669,29.652 39.177,29.652 ; 38.669,29.652 38.669,30.16 ; 38.669,30.16 38.669,30.668 ; 38.669,30.16 38.887,30.16 ; 38.669,30.668 38.669,31.162 ; 38.669,30.668 38.791,30.668 ; 38.669,31.162 38.831,30.999 ; 38.669,35.762 38.829,35.923 38.829,36.256 ; 38.669,35.762 38.669,36.256 ; 38.669,36.256 38.669,36.764 ; 38.669,36.256 38.829,36.256 ; 38.669,36.764 38.829,36.764 ; 38.669,36.764 38.669,36.972 ; 38.669,36.972 ccw(c38.41,37.653) 38.827,37.056 cw(c38.41,37.653) 38.669,36.972 ; 38.669,38.943 38.669,39.304 ; 38.669,38.943 39.03,39.304 ; 38.669,39.304 39.03,39.304 ; 38.669,39.304 38.669,39.369 ccw(c38.024,40.11) 38.958,39.806 ccw(c38.024,40.11) 38.96,39.812 ; 38.669,46.007 cw(c37.93,45.359) 38.745,45.908 ; 38.669,46.007 38.669,46.416 ; 38.669,46.416 38.669,46.924 ; 38.669,46.416 39.177,46.416 ; 38.669,46.924 38.669,47.432 ; 38.669,46.924 39.177,46.924 ; 38.669,47.432 38.669,47.94 ; 38.669,47.432 39.177,47.432 ; 38.669,47.94 38.669,48.448 ; 38.669,47.94 39.177,47.94 ; 38.669,48.448 38.669,48.575 38.669,48.956 ; 38.669,48.448 39.177,48.448 ; 38.669,48.956 38.669,49.114 ; 38.669,48.956 39.177,48.956 ; 38.669,49.114 39.177,49.114 ; 38.705,43.368 cw(c37.973,42.712) 38.944,42.86 ; 38.705,43.368 39.177,43.368 ; 38.726,40.828 ccw(c37.995,41.485) 38.966,41.336 ; 38.726,40.828 39.177,40.828 ; 38.745,45.908 cw(c37.93,45.359) 38.912,45.4 ; 38.745,45.908 39.177,45.908 ; 38.791,30.668 ccw(c40.193,30.668) 38.885,30.166 ccw(c40.193,30.668) 38.887,30.16 ; 38.791,30.668 cw(c40.193,30.668) 38.831,30.999 ; 38.795,44.892 ccw(c37.93,45.359) 38.913,45.359 ccw(c37.93,45.359) 38.912,45.4 ; 38.795,44.892 39.177,44.892 ; 38.829,36.256 38.829,36.764 ; 38.887,42.352 ccw(c37.973,42.712) 38.956,42.712 ccw(c37.973,42.712) 38.944,42.86 ; 38.887,42.352 39.177,42.352 ; 38.9,44.384 cw(c37.967,44.076) 38.949,44.076 cw(c37.967,44.076) 38.929,43.876 ; 38.9,44.384 39.177,44.384 ; 38.91,41.844 cw(c37.995,41.485) 38.912,41.837 cw(c37.995,41.485) 38.978,41.485 cw(c37.995,41.485) 38.966,41.336 ; 38.91,41.844 39.177,41.844 ; 38.912,45.4 39.177,45.4 ; 38.929,43.876 39.177,43.876 ; 38.944,42.86 39.177,42.86 ; 38.96,39.812 ccw(c38.024,40.11) 39.006,40.11 ccw(c38.024,40.11) 38.985,40.314 ccw(c38.024,40.11) 38.983,40.32 ; 38.96,39.812 39.177,39.812 ; 38.966,41.336 39.177,41.336 ; 38.983,40.32 39.177,40.32 ; 39.03,39.304 39.177,39.451 ; 39.177,20.889 39.177,21.016 ; 39.177,20.889 39.685,20.889 ; 39.177,21.016 39.685,21.016 ; 39.177,21.016 39.177,21.524 ; 39.177,21.524 39.177,21.692 ; 39.177,21.524 39.685,21.524 ; 39.177,21.692 39.685,21.692 ; 39.177,26.584 39.177,26.604 ; 39.177,26.584 39.685,26.584 ; 39.177,26.604 39.177,26.891 ; 39.177,26.604 39.685,26.604 ; 39.177,26.891 39.685,26.891 ; 39.177,28.349 39.177,28.636 ; 39.177,28.349 39.685,28.349 ; 39.177,28.636 39.177,29.144 ; 39.177,28.636 39.685,28.636 ; 39.177,29.144 39.177,29.652 ; 39.177,29.144 39.685,29.144 ; 39.177,29.652 39.227,29.652 ; 39.177,39.451 39.177,39.812 ; 39.177,39.451 39.538,39.812 ; 39.177,39.812 39.177,40.32 ; 39.177,39.812 39.538,39.812 ; 39.177,40.32 39.177,40.828 ; 39.177,40.32 39.685,40.32 ; 39.177,40.828 39.177,41.336 ; 39.177,40.828 39.685,40.828 ; 39.177,41.336 39.177,41.844 ; 39.177,41.336 39.685,41.336 ; 39.177,41.844 39.177,42.352 ; 39.177,41.844 39.685,41.844 ; 39.177,42.352 39.177,42.86 ; 39.177,42.352 39.685,42.352 ; 39.177,42.86 39.177,43.368 ; 39.177,42.86 39.685,42.86 ; 39.177,43.368 39.177,43.876 ; 39.177,43.368 39.685,43.368 ; 39.177,43.876 39.177,44.384 ; 39.177,43.876 39.685,43.876 ; 39.177,44.384 39.177,44.892 ; 39.177,44.384 39.685,44.384 ; 39.177,44.892 39.177,45.4 ; 39.177,44.892 39.685,44.892 ; 39.177,45.4 39.177,45.908 ; 39.177,45.4 39.685,45.4 ; 39.177,45.908 39.177,46.416 ; 39.177,45.908 39.685,45.908 ; 39.177,46.416 39.177,46.924 ; 39.177,46.416 39.685,46.416 ; 39.177,46.924 39.177,47.432 ; 39.177,46.924 39.685,46.924 ; 39.177,47.432 39.177,47.94 ; 39.177,47.432 39.685,47.432 ; 39.177,47.94 39.177,48.448 ; 39.177,47.94 39.685,47.94 ; 39.177,48.448 39.177,48.575 39.177,48.956 ; 39.177,48.448 39.685,48.448 ; 39.177,48.956 39.177,49.114 ; 39.177,48.956 39.685,48.956 ; 39.177,49.114 39.685,49.114 ; 39.207,52.004 39.207,52.512 ; 39.207,52.004 39.207,51.817 39.685,51.817 ; 39.207,52.004 39.685,52.004 ; 39.207,52.512 39.626,52.512 ; 39.207,52.512 39.207,53.224 ; 39.207,53.224 ccw(c40.296,53.386) 39.626,52.512 ; 39.227,29.652 ccw(c40.193,30.668) 39.685,29.362 ; 39.538,39.812 39.685,39.959 ; 39.626,52.512 ccw(c40.296,53.386) 39.68,52.473 ccw(c40.296,53.386) 39.685,52.47 ; 39.685,20.889 40.193,20.889 ; 39.685,20.889 39.685,21.016 ; 39.685,21.016 40.193,21.016 ; 39.685,21.016 39.685,21.524 ; 39.685,21.524 40.193,21.524 ; 39.685,21.524 39.685,21.692 ; 39.685,21.692 40.193,21.692 ; 39.685,26.584 39.685,26.604 ; 39.685,26.584 40.193,26.584 ; 39.685,26.604 39.685,26.891 ; 39.685,26.604 40.193,26.604 ; 39.685,26.891 40.193,26.891 ; 39.685,28.349 39.685,28.636 ; 39.685,28.349 40.193,28.349 ; 39.685,28.636 39.685,29.144 ; 39.685,28.636 40.193,28.636 ; 39.685,29.144 40.193,29.144 ; 39.685,29.144 39.685,29.362 ; 39.685,29.362 ccw(c40.193,30.668) 39.691,29.359 ccw(c40.193,30.668) 40.193,29.266 ; 39.685,32.206 39.699,32.192 ; 39.685,32.206 39.572,32.319 39.862,32.608 ; 39.685,39.959 39.685,40.32 ; 39.685,39.959 40.046,40.32 ; 39.685,40.32 39.685,40.828 ; 39.685,40.32 40.046,40.32 ; 39.685,40.828 39.685,41.336 ; 39.685,40.828 40.193,40.828 ; 39.685,41.336 39.685,41.844 ; 39.685,41.336 40.193,41.336 ; 39.685,41.844 39.685,42.352 ; 39.685,41.844 40.193,41.844 ; 39.685,42.352 39.685,42.86 ; 39.685,42.352 40.193,42.352 ; 39.685,42.86 39.685,43.368 ; 39.685,42.86 40.193,42.86 ; 39.685,43.368 39.685,43.876 ; 39.685,43.368 40.193,43.368 ; 39.685,43.876 39.685,44.384 ; 39.685,43.876 40.193,43.876 ; 39.685,44.384 39.685,44.892 ; 39.685,44.384 40.193,44.384 ; 39.685,44.892 39.685,45.4 ; 39.685,44.892 40.193,44.892 ; 39.685,45.4 39.685,45.908 ; 39.685,45.4 40.193,45.4 ; 39.685,45.908 39.685,46.416 ; 39.685,45.908 40.193,45.908 ; 39.685,46.416 39.685,46.924 ; 39.685,46.416 40.193,46.416 ; 39.685,46.924 39.685,47.432 ; 39.685,46.924 40.193,46.924 ; 39.685,47.432 39.685,47.94 ; 39.685,47.432 40.193,47.432 ; 39.685,47.94 39.685,48.448 ; 39.685,47.94 40.193,47.94 ; 39.685,48.448 39.685,48.575 39.685,48.956 ; 39.685,48.448 40.193,48.448 ; 39.685,48.956 39.685,49.114 ; 39.685,48.956 40.193,48.956 ; 39.685,49.114 40.193,49.114 ; 39.685,51.817 39.685,52.004 ; 39.685,51.817 40.193,51.817 ; 39.685,52.004 40.193,52.004 ; 39.685,52.004 39.685,52.47 ; 39.699,32.192 40.193,32.192 ; 39.699,32.192 39.862,32.03 ; 39.862,32.03 cw(c40.193,30.668) 40.193,32.07 ; 39.862,32.608 ccw(c40.193,33.97) 40.193,32.568 ; 40.046,40.32 40.193,40.467 ; 40.193,20.889 40.193,21.016 ; 40.193,20.889 40.701,20.889 ; 40.193,21.016 40.701,21.016 ; 40.193,21.016 40.193,21.524 ; 40.193,21.524 40.193,21.692 ; 40.193,21.524 40.701,21.524 ; 40.193,21.692 40.701,21.692 ; 40.193,26.584 40.193,26.604 ; 40.193,26.584 40.701,26.584 ; 40.193,26.604 40.193,26.891 ; 40.193,26.604 40.701,26.604 ; 40.193,26.891 40.701,26.891 ; 40.193,28.349 40.193,28.636 ; 40.193,28.349 40.701,28.349 ; 40.193,28.636 40.193,29.144 ; 40.193,28.636 40.701,28.636 ; 40.193,29.144 40.701,29.144 ; 40.193,29.144 40.193,29.266 ; 40.193,29.266 ccw(c40.193,30.668) 40.695,29.359 ccw(c40.193,30.668) 40.701,29.362 ; 40.193,32.07 40.193,32.192 ; 40.193,32.192 40.701,32.192 ; 40.193,32.192 40.193,32.568 ; 40.193,32.568 ccw(c40.193,33.97) 40.701,32.664 ; 40.193,40.467 40.554,40.828 ; 40.193,40.467 40.193,40.828 ; 40.193,40.828 40.193,41.336 ; 40.193,40.828 40.554,40.828 ; 40.193,41.336 40.701,41.336 ; 40.193,41.336 40.193,41.844 ; 40.193,41.844 40.193,42.352 ; 40.193,41.844 40.701,41.844 ; 40.193,42.352 40.701,42.352 ; 40.193,42.352 40.193,42.86 ; 40.193,42.86 40.701,42.86 ; 40.193,42.86 40.193,43.368 ; 40.193,43.368 40.701,43.368 ; 40.193,43.368 40.193,43.876 ; 40.193,43.876 40.701,43.876 ; 40.193,43.876 40.193,44.384 ; 40.193,44.384 40.701,44.384 ; 40.193,44.384 40.193,44.892 ; 40.193,44.892 40.701,44.892 ; 40.193,44.892 40.193,45.4 ; 40.193,45.4 40.701,45.4 ; 40.193,45.4 40.193,45.908 ; 40.193,45.908 40.193,46.416 ; 40.193,46.416 40.193,46.924 ; 40.193,46.416 40.316,46.416 ; 40.193,46.924 40.193,47.432 ; 40.193,46.924 40.295,46.924 ; 40.193,47.432 40.193,47.94 ; 40.193,47.432 40.54,47.432 ; 40.193,47.94 40.193,48.448 ; 40.193,47.94 40.701,47.94 ; 40.193,48.448 40.193,48.575 40.193,48.956 ; 40.193,48.448 40.701,48.448 ; 40.193,48.956 40.193,49.114 ; 40.193,48.956 40.701,48.956 ; 40.193,49.114 40.701,49.114 ; 40.193,51.817 40.701,51.817 ; 40.193,51.817 40.193,52.004 ; 40.193,52.004 40.701,52.004 ; 40.295,46.924 ccw(c41.376,46.714) 40.274,46.714 ccw(c41.376,46.714) 40.316,46.416 ; 40.295,46.924 cw(c41.376,46.714) 40.54,47.432 ; 40.316,46.416 ccw(c41.376,46.714) 40.597,45.935 41.132,45.4 ; 40.54,47.432 cw(c41.376,46.714) 40.698,47.582 cw(c41.376,46.714) 40.701,47.585 ; 40.554,40.828 40.701,40.975 ; 40.701,20.889 40.701,21.016 ; 40.701,20.889 41.209,20.889 ; 40.701,21.016 40.701,21.524 ; 40.701,21.016 41.209,21.016 ; 40.701,21.524 40.701,21.692 ; 40.701,21.524 41.209,21.524 ; 40.701,21.692 41.209,21.692 ; 40.701,26.584 41.209,26.584 ; 40.701,26.584 40.701,26.604 ; 40.701,26.604 41.209,26.604 ; 40.701,26.604 40.701,26.891 ; 40.701,26.891 41.209,26.891 ; 40.701,28.349 40.701,28.636 ; 40.701,28.349 40.907,28.349 41.195,28.636 ; 40.701,28.636 40.701,29.144 ; 40.701,28.636 41.195,28.636 ; 40.701,29.144 41.209,29.144 ; 40.701,29.144 40.701,29.362 ; 40.701,29.362 ccw(c40.193,30.668) 41.159,29.652 ; 40.701,32.192 41.209,32.192 ; 40.701,32.192 40.701,32.664 ; 40.701,40.975 40.701,41.336 ; 40.701,40.975 41.062,41.336 ; 40.701,41.336 40.701,41.844 ; 40.701,41.336 41.062,41.336 ; 40.701,41.844 40.701,42.352 ; 40.701,41.844 41.209,41.844 ; 40.701,42.352 40.701,42.86 ; 40.701,42.352 41.209,42.352 ; 40.701,42.86 40.701,43.368 ; 40.701,42.86 41.209,42.86 ; 40.701,43.368 40.701,43.876 ; 40.701,43.368 41.209,43.368 ; 40.701,43.876 41.209,43.876 ; 40.701,43.876 40.701,44.384 ; 40.701,44.384 41.209,44.384 ; 40.701,44.384 40.701,44.892 ; 40.701,44.892 41.209,44.892 ; 40.701,44.892 40.701,45.4 ; 40.701,45.4 41.132,45.4 ; 40.701,47.585 cw(c41.376,46.714) 41.209,47.803 ; 40.701,47.585 40.701,47.94 ; 40.701,47.94 41.209,47.94 ; 40.701,47.94 40.701,48.448 ; 40.701,48.448 41.209,48.448 ; 40.701,48.448 40.701,48.575 40.701,48.956 ; 40.701,48.956 41.209,48.956 ; 40.701,48.956 40.701,49.114 ; 40.701,49.114 41.209,49.114 ; 40.701,51.817 40.701,52.004 ; 40.701,51.817 40.762,51.817 40.949,52.004 ; 40.701,52.004 40.949,52.004 ; 40.701,52.004 40.701,52.362 ; 40.701,52.362 ccw(c40.296,53.386) 40.966,52.512 ; 40.949,52.004 41.209,52.264 ; 40.966,52.512 ccw(c40.296,53.386) 41.209,52.769 ; 40.966,52.512 41.209,52.512 ; 41.062,41.336 41.209,41.483 ; 41.132,45.4 41.209,45.323 ; 41.159,29.652 ccw(c40.193,30.668) 41.201,29.694 ccw(c40.193,30.668) 41.209,29.702 ; 41.159,29.652 41.209,29.652 ; 41.159,31.684 cw(c40.193,30.668) 41.209,31.634 ; 41.159,31.684 41.209,31.684 ; 41.176,35.24 41.209,35.24 ; 41.176,35.24 41.176,35.748 ; 41.176,35.748 41.176,36.256 ; 41.176,35.748 41.209,35.748 ; 41.176,36.256 41.209,36.256 ; 41.176,36.256 41.176,36.764 ; 41.176,36.764 41.209,36.764 ; 41.176,36.764 41.176,37.272 ; 41.176,37.272 41.176,37.78 ; 41.176,37.272 41.209,37.272 ; 41.176,37.78 41.176,37.859 41.604,38.288 ; 41.176,37.78 41.209,37.78 ; 41.195,28.636 41.209,28.65 ; 41.209,20.889 41.209,21.016 ; 41.209,20.889 41.717,20.889 ; 41.209,21.016 41.209,21.524 ; 41.209,21.016 41.717,21.016 ; 41.209,21.524 41.209,21.692 ; 41.209,21.524 41.717,21.524 ; 41.209,21.692 41.717,21.692 ; 41.209,26.584 41.717,26.584 ; 41.209,26.584 41.209,26.604 ; 41.209,26.604 41.717,26.604 ; 41.209,26.604 41.209,26.891 ; 41.209,26.891 ccw(c41.209,27.62) 41.717,27.098 ; 41.209,26.891 ccw(c41.209,27.62) 41.717,27.098 ; 41.209,28.65 41.209,29.144 ; 41.209,28.65 41.703,29.144 ; 41.209,29.144 41.209,29.652 ; 41.209,29.144 41.703,29.144 ; 41.209,29.652 41.717,29.652 ; 41.209,29.652 41.209,29.702 ; 41.209,29.702 ccw(c40.193,30.668) 41.499,30.16 ; 41.209,31.634 cw(c40.193,30.668) 41.499,31.176 ; 41.209,31.634 41.209,31.684 ; 41.209,31.684 41.209,32.192 ; 41.209,31.684 41.717,31.684 ; 41.209,32.192 41.209,32.7 ; 41.209,32.192 41.717,32.192 ; 41.209,32.7 41.717,32.7 ; 41.209,32.7 40.786,32.7 ccw(c40.193,33.97) 41.209,33.004 ; 41.209,32.7 41.209,33.004 ; 41.209,33.004 ccw(c40.193,33.97) 41.368,33.207 ccw(c40.193,33.97) 41.369,33.208 ; 41.209,34.936 cw(c40.193,33.97) 41.38,34.715 ; 41.209,34.936 41.209,35.24 ; 41.209,35.24 41.717,35.24 ; 41.209,35.24 41.209,35.748 ; 41.209,35.748 41.209,36.256 ; 41.209,35.748 41.717,35.748 ; 41.209,36.256 41.717,36.256 ; 41.209,36.256 41.209,36.764 ; 41.209,36.764 41.717,36.764 ; 41.209,36.764 41.209,37.272 ; 41.209,37.272 41.209,37.78 ; 41.209,37.272 41.717,37.272 ; 41.209,37.78 41.717,37.78 ; 41.209,41.483 41.57,41.844 ; 41.209,41.483 41.209,41.844 ; 41.209,41.844 41.209,42.352 ; 41.209,41.844 41.57,41.844 ; 41.209,42.352 41.209,42.86 ; 41.209,42.352 41.717,42.352 ; 41.209,42.86 41.209,43.368 ; 41.209,42.86 41.717,42.86 ; 41.209,43.368 41.209,43.876 ; 41.209,43.368 41.717,43.368 ; 41.209,43.876 pad.@41.717,43.876 ; 41.209,43.876 41.209,44.384 ; 41.209,44.384 pad.@41.717,44.384 ; 41.209,44.384 41.209,44.892 ; 41.209,44.892 41.209,45.323 ; 41.209,44.892 41.646,44.892 ; 41.209,47.803 cw(c41.376,46.714) 41.716,47.762 ; 41.209,47.803 41.209,47.94 ; 41.209,47.94 41.209,48.448 ; 41.209,47.94 41.717,47.94 ; 41.209,48.448 41.209,48.575 41.209,48.956 ; 41.209,48.448 41.717,48.448 ; 41.209,48.956 41.717,48.956 ; 41.209,48.956 41.209,49.114 ; 41.209,49.114 41.322,49.114 ; 41.209,52.264 41.209,52.512 ; 41.209,52.512 41.209,52.769 ; 41.209,52.512 41.468,52.512 ; 41.209,52.769 ccw(c40.296,53.386) 41.21,52.77 ccw(c40.296,53.386) 41.335,53.02 ; 41.322,49.114 ccw(c41.322,50.466) 41.717,49.173 ; 41.322,49.114 ccw(c41.322,50.466) 41.717,49.173 ; 41.335,53.02 ccw(c40.296,53.386) 41.398,53.386 41.398,53.528 ; 41.335,53.02 41.717,53.02 ; 41.369,33.208 41.717,33.208 ; 41.392,56.065 cw(c40.296,55.95) 41.398,55.95 ; 41.392,56.065 cw(c40.296,55.95) 41.398,55.95 ; 41.392,56.065 41.717,56.063 ; 41.398,53.528 41.398,54.036 ; 41.398,53.528 41.717,53.528 ; 41.398,54.036 41.717,54.036 ; 41.398,54.036 41.398,54.544 ; 41.398,54.544 41.717,54.544 ; 41.398,54.544 41.398,55.052 ; 41.398,55.052 41.717,55.052 ; 41.398,55.052 41.398,55.56 ; 41.398,55.56 41.717,55.56 ; 41.398,55.56 41.398,55.95 ; 41.468,52.512 ccw(c42.312,51.456) 41.356,52.412 cw(c42.312,51.456) 41.468,52.512 ; 41.468,52.512 cw(c42.312,51.456) 41.717,52.67 ; 41.468,52.512 cw(c42.312,51.456) 41.717,52.67 ; 41.499,30.16 ccw(c40.193,30.668) 41.595,30.668 ; 41.499,30.16 41.717,30.16 ; 41.499,31.176 cw(c40.193,30.668) 41.502,31.17 cw(c40.193,30.668) 41.595,30.668 ; 41.499,31.176 41.717,31.176 ; 41.57,41.844 41.717,41.991 ; 41.595,30.668 41.717,30.668 ; 41.604,38.288 41.717,38.401 ; 41.604,38.288 41.717,38.288 ; 41.646,44.892 ccw(c42.354,45.737) 41.717,44.838 ; 41.646,44.892 ccw(c42.354,45.737) 41.717,44.838 ; 41.646,44.892 cw(c42.354,45.737) 41.575,44.958 ccw(c42.354,45.737) 41.646,44.892 ; 41.703,29.144 41.717,29.158 ; 41.717,20.889 41.717,21.016 ; 41.717,20.889 42.225,20.889 ; 41.717,21.016 41.717,21.524 ; 41.717,21.016 42.225,21.016 ; 41.717,21.524 41.717,21.692 ; 41.717,21.524 42.225,21.524 ; 41.717,21.692 42.225,21.692 ; 41.717,26.584 42.225,26.584 ; 41.717,26.584 41.717,26.604 ; 41.717,26.604 42.225,26.604 ; 41.717,26.604 41.717,27.098 ; 41.717,27.098 ccw(c41.209,27.62) 41.724,27.105 ; 41.717,27.098 ccw(c41.209,27.62) 41.724,27.105 ; 41.717,29.158 42.225,29.666 ; 41.717,29.158 41.717,29.652 ; 41.717,29.652 41.717,30.16 ; 41.717,30.16 41.717,30.668 ; 41.717,30.16 42.225,30.16 ; 41.717,30.668 41.717,31.176 ; 41.717,30.668 42.225,30.668 ; 41.717,31.176 41.717,31.684 ; 41.717,31.176 42.225,31.176 ; 41.717,31.684 41.717,32.192 ; 41.717,31.684 42.225,31.684 ; 41.717,32.192 41.717,32.7 ; 41.717,32.192 42.225,32.192 ; 41.717,32.7 41.717,33.208 ; 41.717,32.7 42.225,32.7 ; 41.717,33.208 42.225,33.208 ; 41.717,33.208 41.717,33.604 ; 41.717,33.604 ccw(c42.307,34.389) 42.222,33.41 ccw(c42.307,34.389) 42.225,33.41 ; 41.717,35.24 41.717,35.748 ; 41.717,35.24 41.717,35.175 cw(c42.307,34.389) 41.816,35.24 ; 41.717,35.24 41.816,35.24 ; 41.717,35.748 41.717,36.256 ; 41.717,35.748 42.225,35.748 ; 41.717,36.256 42.225,36.256 ; 41.717,36.256 41.717,36.764 ; 41.717,36.764 42.225,36.764 ; 41.717,36.764 41.717,37.272 ; 41.717,37.272 41.717,37.78 ; 41.717,37.272 42.225,37.272 ; 41.717,37.78 41.717,38.288 ; 41.717,37.78 42.225,37.78 ; 41.717,38.288 41.717,38.401 ; 41.717,38.288 42.225,38.288 ; 41.717,38.401 42.097,38.781 ; 41.717,41.991 41.717,42.352 ; 41.717,41.991 41.861,42.135 ; 41.717,42.352 41.717,42.86 ; 41.717,42.352 42.225,42.352 ; 41.717,42.86 41.717,43.368 ; 41.717,42.86 42.225,42.86 ; 41.717,43.368 pad.@41.717,43.876 ; 41.717,43.368 42.225,43.368 ; pad.@41.717,43.876 pad.@41.717,44.384 ; pad.@41.717,43.876 pad.@42.225,43.876 ; pad.@41.717,44.384 41.717,44.838 ; pad.@41.717,44.384 pad.@42.225,44.384 ; 41.717,44.838 ccw(c42.354,45.737) 42.225,44.643 ; 41.717,44.838 ccw(c42.354,45.737) 42.225,44.643 ; 41.717,47.762 cw(c41.376,46.714) 42.155,47.493 42.216,47.432 ; 41.717,47.762 41.717,47.94 ; 41.717,47.94 42.225,47.94 ; 41.717,47.94 41.717,48.448 ; 41.717,48.448 42.225,48.448 ; 41.717,48.448 41.717,48.575 41.717,48.956 ; 41.717,48.956 42.225,48.956 ; 41.717,48.956 41.717,49.173 ; 41.717,49.173 ccw(c41.322,50.466) 42.225,49.46 ; 41.717,49.173 ccw(c41.322,50.466) 42.225,49.46 ; 41.717,52.67 cw(c42.312,51.456) 41.72,52.671 ; 41.717,52.67 cw(c42.312,51.456) 41.72,52.671 ; 41.717,52.67 41.717,53.02 ; 41.717,53.02 42.225,53.02 ; 41.717,53.02 41.717,53.528 ; 41.717,53.528 42.225,53.528 ; 41.717,53.528 41.717,54.036 ; 41.717,54.036 41.717,54.544 ; 41.717,54.036 42.225,54.036 ; 41.717,54.544 41.717,55.052 ; 41.717,54.544 42.225,54.544 ; 41.717,55.052 41.717,55.56 ; 41.717,55.052 42.225,55.052 ; 41.717,55.56 41.717,56.063 ; 41.717,55.56 42.225,55.56 ; 41.717,56.063 42.225,56.059 ; 41.72,52.671 cw(c42.312,51.456) 42.225,52.805 ; 41.72,52.671 cw(c42.312,51.456) 42.225,52.805 ; 41.724,27.105 41.731,27.112 ; 41.731,27.112 42.239,27.62 ; 41.731,27.112 42.225,27.112 ; 41.816,35.24 cw(c42.307,34.389) 42.225,35.368 ; 41.861,42.135 cw(c42.376,41.62) 42.225,42.332 ; 41.861,42.135 cw(c42.376,41.62) 42.225,42.332 ; 42.097,38.781 ccw(c42.625,39.609) 42.225,38.712 ; 42.216,47.432 42.225,47.423 ; 42.216,47.432 42.225,47.432 ; 42.225,20.889 42.225,21.016 ; 42.225,20.889 42.733,20.889 ; 42.225,21.016 42.225,21.524 ; 42.225,21.016 42.733,21.016 ; 42.225,21.524 42.225,21.692 ; 42.225,21.524 42.733,21.524 ; 42.225,21.692 42.733,21.692 ; 42.225,26.584 42.225,26.604 ; 42.225,26.584 42.571,26.584 44.765,28.777 ; 42.225,26.604 42.225,27.112 ; 42.225,27.112 42.733,27.112 ; 42.225,29.666 42.733,30.174 ; 42.225,29.666 42.225,30.16 ; 42.225,30.16 42.225,30.668 ; 42.225,30.668 42.733,30.668 ; 42.225,30.668 42.225,31.176 ; 42.225,31.176 42.225,31.684 ; 42.225,31.176 42.733,31.176 ; 42.225,31.684 42.733,31.684 ; 42.225,31.684 42.225,32.192 ; 42.225,32.192 42.733,32.192 ; 42.225,32.192 42.225,32.7 ; 42.225,32.7 42.225,33.208 ; 42.225,32.7 42.733,32.7 ; 42.225,33.208 42.733,33.208 ; 42.225,33.208 42.225,33.41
